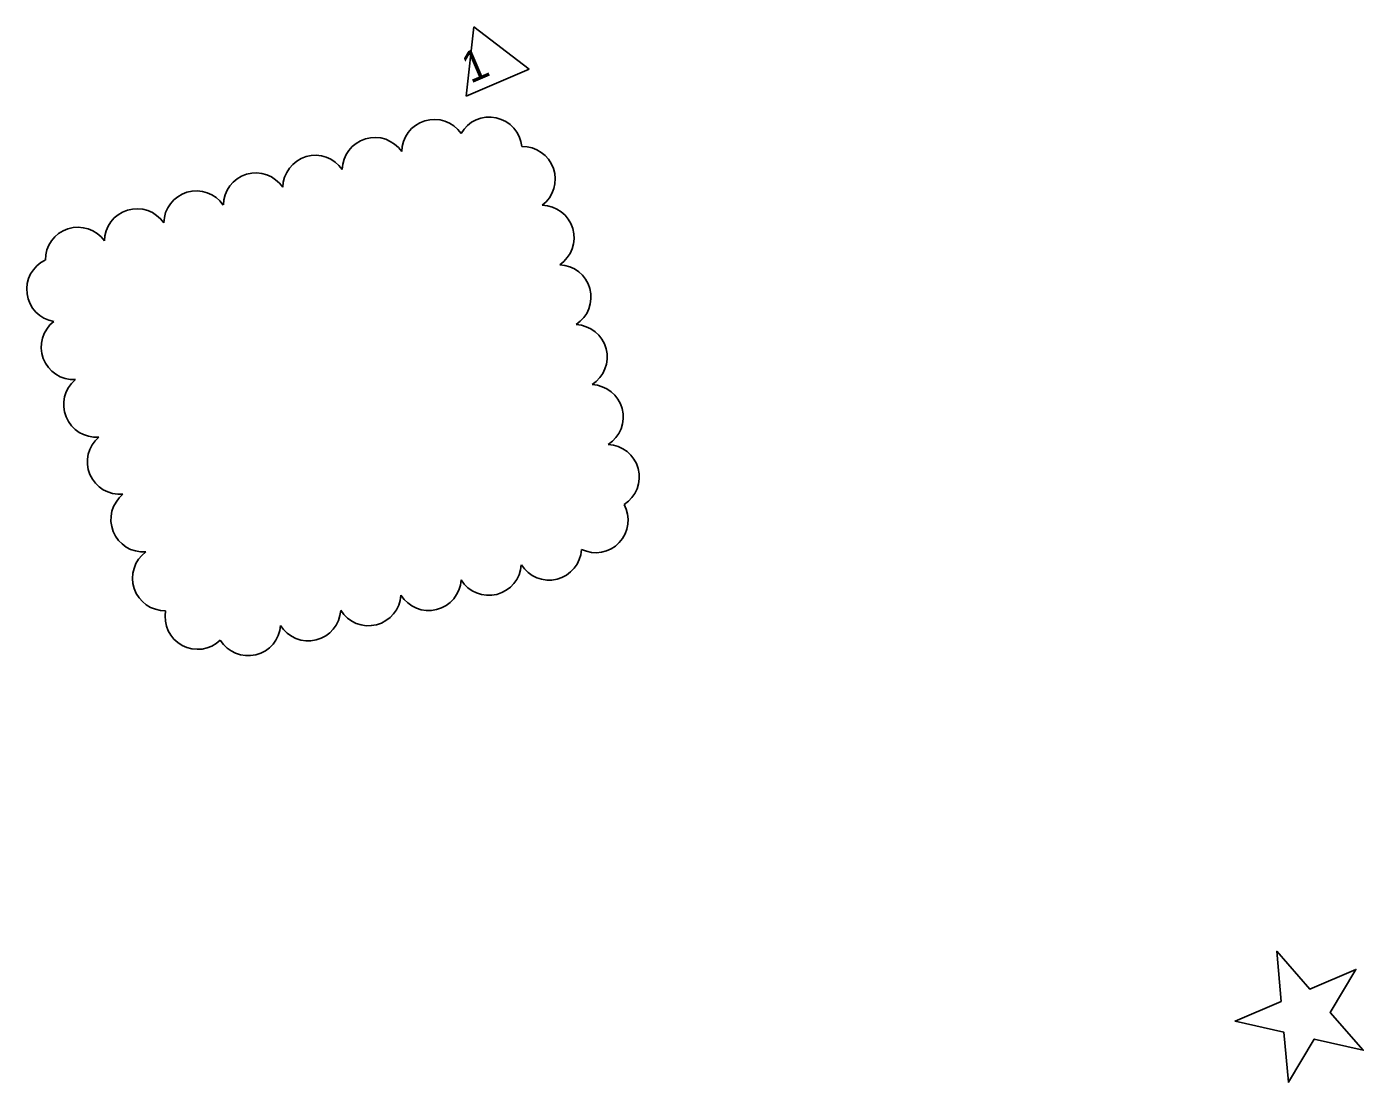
# Model space of a CAD drawing. Extents: x 2192740 to 2194721, y 86011 to 87688.
# Drawn here: x 2193870.2 to 2194063.4, y 86871 to 87023.7 of the extents above; entities that cross this region are included whole.
import ezdxf

# ---------------------------------------------------------------- set-up
doc = ezdxf.new("R2010")
doc.units = 0
doc.layers.add('Exist Roads Curbs', color=7, linetype='Continuous')
doc.layers.add('Old_Level_6', color=7, linetype='Continuous')

msp = doc.modelspace()

# ---------------------------------------------------------------- linework, layer by layer
at = {"layer": 'Exist Roads Curbs'}
msp.add_lwpolyline([(2194051.57, 86882.7), (2194044.9, 86879.85), (2194051.97, 86878.24), (2194052.62, 86871), (2194056.35, 86877.24), (2194063.43, 86875.62), (2194058.66, 86881.09), (2194062.38, 86887.32), (2194055.7, 86884.47), (2194050.92, 86889.94), (2194051.57, 86882.7)], dxfattribs=at)
at = {"layer": 'Old_Level_6'}
for p, q in [((2193933.74, 87013.63), (2193934.85, 87023.67)), ((2193934.85, 87023.67), (2193942.88, 87017.53)), ((2193933.74, 87013.63), (2193942.88, 87017.53))]:
    msp.add_line(p, q, dxfattribs=at)
for centre, radius, start, end in [((2193929.14, 87005.57), 4.7, 34.5266, 179.5266), ((2193937.1, 87005.9), 4.7, 5.2514, 150.2514), ((2193920.55, 87002.96), 4.7, 34.2494, 179.2494), ((2193941.93, 87001.63), 4.7, 306.7119, 91.7119), ((2193911.95, 87000.38), 4.7, 34.1193, 179.1193), ((2193903.35, 86997.82), 4.7, 34.0975, 179.0975), ((2193894.75, 86995.24), 4.7, 34.2163, 179.2163), ((2193944.65, 86993.15), 4.7, 303.9642, 88.9642), ((2193886.17, 86992.65), 4.7, 34.4453, 179.4453), ((2193877.63, 86989.96), 4.71, 35.4319, 180.4319), ((2193874.93, 86985.68), 4.7, 115.3312, 260.3312), ((2193947.1, 86984.55), 4.7, 302.8244, 87.8244), ((2193877.03, 86977.33), 4.7, 127.7927, 272.7927), ((2193949.44, 86975.89), 4.7, 302.4413, 87.4413), ((2193880.26, 86969.01), 4.7, 129.7473, 274.7473), ((2193951.76, 86967.22), 4.7, 302.4413, 87.4413), ((2193883.7, 86960.74), 4.7, 130.3459, 275.3459), ((2193954.07, 86958.55), 4.7, 302.4413, 87.4413), ((2193887.1, 86952.4), 4.7, 129.111, 274.111), ((2193952.48, 86952.3), 4.7, 244.0789, 29.0789), ((2193890.22, 86943.91), 4.7, 126.12, 271.12), ((2193945.73, 86948.33), 4.7, 211.7126, 356.7126), ((2193937.03, 86946.13), 4.7, 211.7126, 356.7126), ((2193928.33, 86943.93), 4.7, 211.7126, 356.7126), ((2193919.63, 86941.73), 4.7, 211.6771, 356.6771), ((2193894.93, 86938.32), 4.7, 169.1641, 314.1641), ((2193910.93, 86939.54), 4.7, 211.5392, 356.5392), ((2193902.23, 86937.39), 4.7, 211.26, 356.26)]:
    msp.add_arc(centre, radius, start, end, dxfattribs=at)

# ---------------------------------------------------------------- texts
msp.add_text(' 1', height=4.5, rotation=23.1206, dxfattribs=at).set_placement((2193932.83, 87014.75))

doc.saveas('drawing.dxf')
